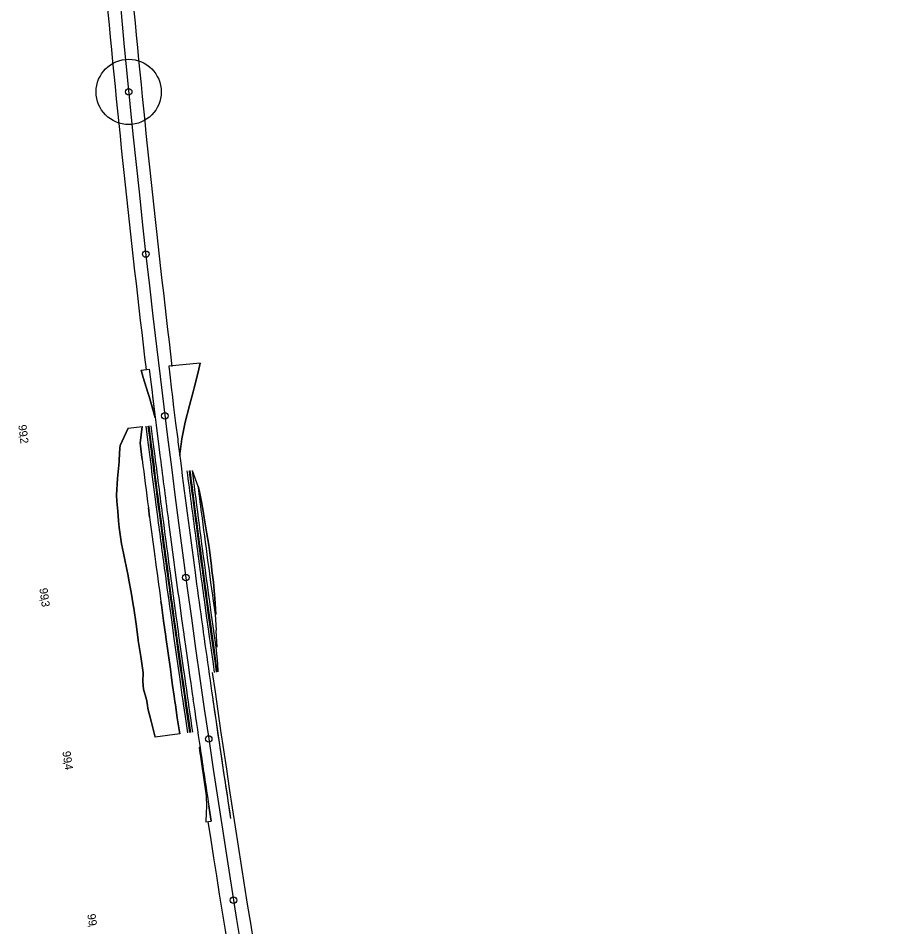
# Model space of a CAD drawing. Extents: x -678487 to -674601, y -1104811 to -1093295.
# Drawn here: x -677497 to -676952, y -1096306 to -1095749 of the extents above; entities that cross this region are included whole.
import ezdxf

# ---------------------------------------------------------------- set-up
doc = ezdxf.new("R2010")
doc.units = 0
for name, color, linetype in [('00_MiNGO', 7, 'Continuous'), ('SOxxxxxx_Osa_bod_P', 7, 'Continuous'), ('SOxxxxxx_Staničení_Popis', 7, 'Continuous'), ('SOxxxxxx_Staničení_Popis10', 7, 'Continuous'), ('SOxxxxxx_ŽSp_hrana', 7, 'Continuous'), ('SOxxxxxx_ŽSp_násyp_hrana', 7, 'Continuous'), ('SOxxxxxx_ŽSp_násyp_plocha', 7, 'Continuous'), ('SOxxxxxx_ŽSp_odvodnění', 7, 'Continuous'), ('SOxxxxxx_ŽSp_zářez_hrana', 7, 'Continuous'), ('SOxxxxxx_ŽSp_zářez_plocha', 7, 'Continuous')]:
    doc.layers.add(name, color=color, linetype=linetype)

msp = doc.modelspace()

# ---------------------------------------------------------------- linework, layer by layer
at = {"layer": '00_MiNGO'}
for radius, start, end in [(8494.25, 185.221143, 186.854762), (8510.25, 185.218154, 186.854762), (8494.25, 188.132648, 193.297784), (8510.25, 188.739149, 193.586695)]:
    msp.add_arc((-668968.6, -1094948.57), radius, start, end, dxfattribs=at)
at = {"layer": 'SOxxxxxx_Osa_bod_P'}
msp.add_arc((-668968.6, -1094948.57), 8502.25, 183.991255, 200.113006, dxfattribs=at)
at = {"layer": 'SOxxxxxx_Staničení_Popis'}
for p, q in [((-677428.71, -1095793.99), (-677428.71, -1095793.99)), ((-677418.18, -1095893.44), (-677418.18, -1095893.44)), ((-677406.48, -1095992.75), (-677406.48, -1095992.75)), ((-677393.62, -1096091.92), (-677393.62, -1096091.92)), ((-677379.59, -1096190.93), (-677379.59, -1096190.93)), ((-677364.39, -1096289.77), (-677364.39, -1096289.77))]:
    msp.add_line(p, q, dxfattribs=at)
for centre in [(-677428.71, -1095793.99), (-677418.18, -1095893.44), (-677406.48, -1095992.75), (-677393.62, -1096091.92), (-677379.59, -1096190.93), (-677364.39, -1096289.77)]:
    msp.add_circle(centre, 2, dxfattribs=at)
at = {"layer": 'SOxxxxxx_Staničení_Popis10'}
msp.add_line((-677428.71, -1095793.99), (-677428.71, -1095793.99), dxfattribs=at)
msp.add_circle((-677428.71, -1095793.99), 20, dxfattribs=at)
at = {"layer": 'SOxxxxxx_ŽSp_hrana'}
for p, q in [((-677416.04, -1095964.06), (-677415.47, -1095968.73)), ((-677415.47, -1095968.73), (-677414.33, -1095978.14)), ((-677414.33, -1095978.14), (-677414.04, -1095980.56)), ((-677414.04, -1095980.56), (-677413.06, -1095988.54)), ((-677413.06, -1095988.54), (-677411.83, -1095998.45)), ((-677411.83, -1095998.45), (-677410.59, -1096008.35)), ((-677410.59, -1096008.35), (-677410.4, -1096009.93)), ((-677410.4, -1096009.93), (-677409.49, -1096017.12)), ((-677409.49, -1096017.12), (-677409.35, -1096018.25)), ((-677387.98, -1096088.76), (-677387, -1096095.96)), ((-677397.59, -1096107.27), (-677396.22, -1096117.15)), ((-677396.22, -1096117.15), (-677394.9, -1096126.67)), ((-677394.9, -1096126.67), (-677394.85, -1096127.03)), ((-677394.85, -1096127.03), (-677393.46, -1096136.91)), ((-677382.97, -1096125.19), (-677382.92, -1096125.55)), ((-677393.46, -1096136.91), (-677392.06, -1096146.79)), ((-677392.06, -1096146.79), (-677391.32, -1096151.99)), ((-677391.32, -1096151.99), (-677390.65, -1096156.66)), ((-677390.65, -1096156.66), (-677389.72, -1096163.14)), ((-677389.72, -1096163.14), (-677389.23, -1096166.53)), ((-677379.51, -1096231.92), (-677378.88, -1096236.02)), ((-677378.88, -1096236.02), (-677378.07, -1096241.31))]:
    msp.add_line(p, q, dxfattribs=at)
for points in [[(-677404.15, -1095962.21), (-677403.51, -1095967.54), (-677402.37, -1095976.93), (-677402.08, -1095979.35), (-677401.1, -1095987.32), (-677399.88, -1095997.2), (-677398.64, -1096007.09), (-677398.44, -1096008.66), (-677397.54, -1096015.84)], [(-677378.73, -1096155.13), (-677377.8, -1096161.6), (-677377.31, -1096164.98)]]:
    msp.add_lwpolyline(points, dxfattribs=at)
for centre, radius, start, end in [((-668968.1, -1094948.47), 8496.75, 187.216621, 187.712543), ((-668969.09, -1094948.67), 8507.75, 187.222244, 187.491036), ((-668969.1, -1094948.67), 8507.75, 187.491036, 187.826977), ((-668968.09, -1094948.47), 8496.75, 187.761534, 187.960504), ((-668968.09, -1094948.47), 8496.75, 187.962972, 188.164393), ((-668969.1, -1094948.67), 8507.75, 188.230039, 188.431546), ((-668968.09, -1094948.47), 8496.75, 188.231529, 188.740385), ((-668969.1, -1094948.67), 8507.75, 188.431546, 188.675191)]:
    msp.add_arc(centre, radius, start, end, dxfattribs=at)
at = {"layer": 'SOxxxxxx_ŽSp_násyp_hrana'}
for p, q in [((-677384.85, -1095960.31), (-677386.16, -1095965.81)), ((-677421.13, -1095964.67), (-677419.76, -1095969.15)), ((-677386.16, -1095965.81), (-677388.5, -1095975.53)), ((-677419.76, -1095969.15), (-677416.94, -1095978.4)), ((-677388.5, -1095975.53), (-677389.16, -1095978.04)), ((-677416.94, -1095978.4), (-677416.23, -1095980.79)), ((-677416.23, -1095980.79), (-677413.93, -1095988.63)), ((-677389.16, -1095978.04), (-677391.32, -1095986.31)), ((-677391.32, -1095986.31), (-677393.99, -1095996.59)), ((-677393.99, -1095996.59), (-677396.09, -1096006.82)), ((-677396.33, -1096008.44), (-677397.23, -1096015.81)), ((-677396.09, -1096006.82), (-677396.33, -1096008.44)), ((-677397.23, -1096015.81), (-677397.36, -1096016.96)), ((-677378.73, -1096155.13), (-677377.8, -1096161.6)), ((-677377.8, -1096161.6), (-677377.31, -1096164.98)), ((-677377.31, -1096164.98), (-677377.01, -1096167.03)), ((-677377.01, -1096167.03), (-677375.88, -1096174.84)), ((-677375.88, -1096174.84), (-677374.43, -1096184.69)), ((-677374.43, -1096184.69), (-677372.98, -1096194.53)), ((-677372.98, -1096194.53), (-677372.37, -1096198.65)), ((-677385.53, -1096196.23), (-677385.04, -1096199.68)), ((-677385.04, -1096199.68), (-677384.93, -1096200.35)), ((-677384.93, -1096200.35), (-677384, -1096206.08)), ((-677372.37, -1096198.65), (-677371.51, -1096204.38)), ((-677384, -1096206.08), (-677382.66, -1096215.97)), ((-677371.51, -1096204.38), (-677370.04, -1096214.23)), ((-677382.66, -1096215.97), (-677381.15, -1096225.82)), ((-677370.04, -1096214.23), (-677368.55, -1096224.07)), ((-677381.15, -1096225.82), (-677380.9, -1096232.11)), ((-677368.55, -1096224.07), (-677367.61, -1096230.24)), ((-677380.9, -1096232.11), (-677381.07, -1096236.33)), ((-677367.61, -1096230.24), (-677366.98, -1096234.34)), ((-677366.98, -1096234.34), (-677366.17, -1096239.62)), ((-677381.07, -1096236.33), (-677381.29, -1096241.76))]:
    msp.add_line(p, q, dxfattribs=at)
at = {"layer": 'SOxxxxxx_ŽSp_násyp_plocha'}
for p, q in [((-677384.85, -1095960.31), (-677404.15, -1095962.21)), ((-677421.13, -1095964.67), (-677416.04, -1095964.06)), ((-677384.89, -1096196.14), (-677385.53, -1096196.23)), ((-677381.29, -1096241.76), (-677378.07, -1096241.31))]:
    msp.add_line(p, q, dxfattribs=at)
for points in [[(-677397.38, -1096017.05), (-677396.33, -1096008.44), (-677396.09, -1096006.82), (-677393.99, -1095996.59), (-677391.32, -1095986.31), (-677389.16, -1095978.04), (-677388.5, -1095975.53), (-677386.16, -1095965.81), (-677384.85, -1095960.31)], [(-677412.41, -1095993.85), (-677416.23, -1095980.79), (-677416.94, -1095978.4), (-677419.76, -1095969.15), (-677421.13, -1095964.67)], [(-677416.04, -1095964.06), (-677415.47, -1095968.73), (-677414.33, -1095978.14), (-677414.04, -1095980.56), (-677412.41, -1095993.85)], [(-677404.15, -1095962.21), (-677403.51, -1095967.54), (-677402.37, -1095976.93), (-677402.08, -1095979.35), (-677401.1, -1095987.32), (-677399.88, -1095997.2), (-677398.64, -1096007.09), (-677398.44, -1096008.66), (-677397.54, -1096015.84)], [(-677385.53, -1096196.23), (-677385.04, -1096199.68), (-677384.93, -1096200.35), (-677384, -1096206.08), (-677382.66, -1096215.97), (-677381.15, -1096225.82), (-677380.9, -1096232.11), (-677381.07, -1096236.33), (-677381.29, -1096241.76)], [(-677378.07, -1096241.31), (-677378.88, -1096236.02), (-677379.51, -1096231.92)]]:
    msp.add_lwpolyline(points, dxfattribs=at)
for centre, radius, start, end in [((-668968.1, -1094948.47), 8496.75, 187.216621, 187.224797), ((-668969.1, -1094948.67), 8507.75, 188.431546, 188.675191)]:
    msp.add_arc(centre, radius, start, end, dxfattribs=at)
at = {"layer": 'SOxxxxxx_ŽSp_odvodnění'}
for p, q in [((-677416.85, -1095998.97), (-677415.62, -1096008.88)), ((-677416.31, -1095998.91), (-677415.07, -1096008.82)), ((-677415.62, -1096008.88), (-677415.42, -1096010.46)), ((-677415.07, -1096008.82), (-677414.87, -1096010.4)), ((-677410.81, -1096042.19), (-677410, -1096048.44)), ((-677406.08, -1096078.13), (-677404.75, -1096088.03)), ((-677404.75, -1096088.03), (-677404.39, -1096090.7)), ((-677404.39, -1096090.7), (-677403.41, -1096097.92)), ((-677403.41, -1096097.92), (-677402.34, -1096105.72)), ((-677402.34, -1096105.72), (-677402.05, -1096107.81)), ((-677381.47, -1096103.2), (-677381.19, -1096105.29)), ((-677381.19, -1096105.29), (-677379.82, -1096115.14)), ((-677380.93, -1096103.14), (-677380.64, -1096105.22)), ((-677380.64, -1096105.22), (-677379.28, -1096115.08)), ((-677402.05, -1096107.81), (-677400.69, -1096117.7)), ((-677379.82, -1096115.14), (-677378.5, -1096124.64)), ((-677379.28, -1096115.08), (-677377.96, -1096124.57)), ((-677400.69, -1096117.7), (-677399.36, -1096127.22)), ((-677399.91, -1096127.29), (-677399.86, -1096127.65)), ((-677399.86, -1096127.65), (-677398.47, -1096137.54)), ((-677399.36, -1096127.22), (-677399.31, -1096127.59)), ((-677399.31, -1096127.59), (-677397.92, -1096137.47)), ((-677378.5, -1096124.64), (-677378.45, -1096125)), ((-677378.45, -1096125), (-677377.07, -1096134.85)), ((-677377.96, -1096124.57), (-677377.91, -1096124.93)), ((-677377.91, -1096124.93), (-677376.52, -1096134.78)), ((-677398.47, -1096137.54), (-677397.07, -1096147.42)), ((-677397.92, -1096137.47), (-677396.52, -1096147.35)), ((-677377.07, -1096134.85), (-677375.67, -1096144.7)), ((-677376.52, -1096134.78), (-677375.13, -1096144.64)), ((-677375.67, -1096144.7), (-677374.93, -1096149.89)), ((-677375.13, -1096144.64), (-677374.39, -1096149.82)), ((-677397.07, -1096147.42), (-677396.33, -1096152.63)), ((-677396.52, -1096147.35), (-677395.78, -1096152.56)), ((-677396.33, -1096152.63), (-677395.66, -1096157.31)), ((-677395.78, -1096152.56), (-677395.11, -1096157.24)), ((-677395.66, -1096157.31), (-677394.73, -1096163.79)), ((-677395.11, -1096157.24), (-677394.18, -1096163.72)), ((-677394.73, -1096163.79), (-677394.24, -1096167.19)), ((-677394.24, -1096167.19), (-677393.94, -1096169.24)), ((-677394.18, -1096163.72), (-677393.69, -1096167.11)), ((-677393.69, -1096167.11), (-677393.39, -1096169.17)), ((-677393.94, -1096169.24), (-677392.8, -1096177.06)), ((-677393.39, -1096169.17), (-677392.26, -1096176.99)), ((-677392.8, -1096177.06), (-677391.35, -1096186.94)), ((-677392.26, -1096176.99), (-677390.81, -1096186.87))]:
    msp.add_line(p, q, dxfattribs=at)
for centre, radius, start, end in [((-668969.51, -1094948.75), 8512.38, 187.164886, 187.380633), ((-668969.47, -1094948.74), 8511.87, 187.16498, 187.380722), ((-668967.72, -1094948.4), 8492.63, 187.292183, 187.56077), ((-668967.67, -1094948.39), 8492.13, 187.292275, 187.560855), ((-668969.51, -1094948.75), 8512.38, 187.380633, 187.557454), ((-668969.47, -1094948.74), 8511.87, 187.423125, 187.624742), ((-668967.72, -1094948.4), 8492.63, 187.56077, 187.81513), ((-668967.67, -1094948.39), 8492.13, 187.560855, 187.815209), ((-668969.51, -1094948.75), 8512.37, 187.557454, 187.759064), ((-668969.52, -1094948.75), 8512.37, 187.759064, 187.958184)]:
    msp.add_arc(centre, radius, start, end, dxfattribs=at)
at = {"layer": 'SOxxxxxx_ŽSp_zářez_hrana'}
for p, q in [((-677428.97, -1096000.23), (-677433.98, -1096010.82)), ((-677415.03, -1095998.78), (-677413.8, -1096008.69)), ((-677433.98, -1096010.82), (-677434.2, -1096012.44)), ((-677413.8, -1096008.69), (-677413.6, -1096010.26)), ((-677413.6, -1096010.26), (-677412.69, -1096017.46)), ((-677434.2, -1096012.44), (-677434.49, -1096019.79)), ((-677434.61, -1096020.95), (-677435.65, -1096031.14)), ((-677434.49, -1096019.79), (-677434.61, -1096020.95)), ((-677389.84, -1096026.17), (-677388.57, -1096036.03)), ((-677389.75, -1096026.15), (-677386.27, -1096035.78)), ((-677435.65, -1096031.14), (-677436.27, -1096041.29)), ((-677388.57, -1096036.03), (-677388.1, -1096039.68)), ((-677386.13, -1096035.77), (-677385.33, -1096039.37)), ((-677436.27, -1096041.29), (-677436.05, -1096044.99)), ((-677385.33, -1096039.37), (-677383.98, -1096045.53)), ((-677436.05, -1096044.99), (-677435.46, -1096051.28)), ((-677415.86, -1096054.91), (-677416.61, -1096049.18)), ((-677383.98, -1096045.53), (-677383, -1096051.21)), ((-677435.46, -1096051.28), (-677434.91, -1096057.05)), ((-677383, -1096051.21), (-677382.31, -1096055.35)), ((-677382.31, -1096055.35), (-677380.65, -1096065.17)), ((-677434.91, -1096057.05), (-677434.5, -1096061.26)), ((-677434.5, -1096061.26), (-677433.06, -1096071.18)), ((-677380.65, -1096065.17), (-677379.69, -1096070.85)), ((-677433.06, -1096071.18), (-677431.92, -1096076.89)), ((-677383.94, -1096071.34), (-677383.38, -1096075.49)), ((-677379.69, -1096070.85), (-677379.13, -1096075)), ((-677431.92, -1096076.89), (-677431.09, -1096081.04)), ((-677379.13, -1096075), (-677377.92, -1096084.87)), ((-677431.09, -1096081.04), (-677429.11, -1096090.9)), ((-677403.48, -1096087.88), (-677403.12, -1096090.55)), ((-677379.75, -1096085.08), (-677379.39, -1096087.75)), ((-677379.39, -1096087.75), (-677378.42, -1096094.94)), ((-677377.92, -1096084.87), (-677377.59, -1096087.53)), ((-677377.59, -1096087.53), (-677376.7, -1096094.73)), ((-677429.11, -1096090.9), (-677428.55, -1096093.56)), ((-677428.55, -1096093.56), (-677427.27, -1096100.77)), ((-677378.42, -1096094.94), (-677377.35, -1096102.71)), ((-677376.7, -1096094.73), (-677376.07, -1096102.55)), ((-677427.27, -1096100.77), (-677425.99, -1096108.57)), ((-677382.74, -1096103.36), (-677382.46, -1096105.44)), ((-677382.46, -1096105.44), (-677381.1, -1096115.3)), ((-677379.66, -1096102.98), (-677379.37, -1096105.07)), ((-677379.37, -1096105.07), (-677378.01, -1096114.92)), ((-677377.35, -1096102.71), (-677377.07, -1096104.79)), ((-677377.07, -1096104.79), (-677375.71, -1096114.64)), ((-677376.07, -1096102.55), (-677375.92, -1096104.65)), ((-677375.92, -1096104.65), (-677375.18, -1096114.58)), ((-677425.99, -1096108.57), (-677425.64, -1096110.66)), ((-677425.64, -1096110.66), (-677424.07, -1096120.56)), ((-677381.1, -1096115.3), (-677379.77, -1096124.8)), ((-677378.01, -1096114.92), (-677376.69, -1096124.41)), ((-677375.71, -1096114.64), (-677374.92, -1096124.19)), ((-677424.07, -1096120.56), (-677422.91, -1096130.14)), ((-677398.09, -1096127.07), (-677398.04, -1096127.43)), ((-677398.04, -1096127.43), (-677396.65, -1096137.31)), ((-677379.77, -1096124.8), (-677379.72, -1096125.16)), ((-677379.72, -1096125.16), (-677378.34, -1096135.01)), ((-677376.69, -1096124.41), (-677376.64, -1096124.77)), ((-677376.64, -1096124.77), (-677375.25, -1096134.63)), ((-677374.92, -1096124.19), (-677375.3, -1096124.61)), ((-677375.3, -1096124.61), (-677374.55, -1096134.52)), ((-677422.91, -1096130.14), (-677422.87, -1096130.51)), ((-677422.87, -1096130.51), (-677421.33, -1096140.39)), ((-677396.65, -1096137.31), (-677395.25, -1096147.19)), ((-677378.34, -1096135.01), (-677376.94, -1096144.87)), ((-677375.25, -1096134.63), (-677374.27, -1096144.53)), ((-677374.55, -1096134.52), (-677374.55, -1096134.54)), ((-677421.33, -1096140.39), (-677421.33, -1096140.41)), ((-677421.33, -1096140.41), (-677419.79, -1096150.31)), ((-677376.94, -1096144.87), (-677376.2, -1096150.06)), ((-677374.27, -1096144.53), (-677373.98, -1096149.77)), ((-677419.79, -1096150.31), (-677420.12, -1096155.67)), ((-677395.25, -1096147.19), (-677394.51, -1096152.4)), ((-677420.12, -1096155.67), (-677419.52, -1096160.37)), ((-677394.51, -1096152.4), (-677393.84, -1096157.07)), ((-677419.52, -1096160.37), (-677417.76, -1096166.78)), ((-677417.76, -1096166.78), (-677417.1, -1096170.16)), ((-677417.1, -1096170.16), (-677416.87, -1096172.23)), ((-677416.87, -1096172.23), (-677414.97, -1096179.98)), ((-677414.97, -1096179.98), (-677412.4, -1096189.74))]:
    msp.add_line(p, q, dxfattribs=at)
for points in [[(-677420.43, -1096019.44), (-677420.57, -1096018.31), (-677421.48, -1096011.1), (-677421.68, -1096009.52), (-677420.43, -1095999.34)], [(-677418.13, -1095999.1), (-677416.89, -1096009.01), (-677416.69, -1096010.59), (-677415.78, -1096017.79)], [(-677412.63, -1096042.39), (-677411.82, -1096048.64), (-677411.07, -1096054.37)], [(-677406.57, -1096088.24), (-677406.21, -1096090.92), (-677405.22, -1096098.14), (-677404.16, -1096105.94), (-677403.87, -1096108.03), (-677402.51, -1096117.92), (-677401.18, -1096127.45), (-677401.13, -1096127.81), (-677399.74, -1096137.7), (-677398.34, -1096147.59), (-677397.6, -1096152.79), (-677396.93, -1096157.47), (-677395.99, -1096163.96), (-677395.5, -1096167.35), (-677395.21, -1096169.41), (-677394.07, -1096177.23), (-677392.62, -1096187.11)], [(-677397.4, -1096187.75), (-677398.85, -1096177.86), (-677399.99, -1096170.03), (-677400.28, -1096167.97), (-677400.77, -1096164.58), (-677401.71, -1096158.08), (-677402.38, -1096153.4), (-677403.12, -1096148.19), (-677404.52, -1096138.3), (-677405.91, -1096128.4), (-677405.96, -1096128.04), (-677407.29, -1096118.51), (-677408.66, -1096108.61), (-677408.94, -1096106.52)]]:
    msp.add_lwpolyline(points, dxfattribs=at)
for centre, radius, start, end in [((-668970.02, -1094948.85), 8517.96, 187.220371, 187.422067), ((-668969.62, -1094948.77), 8513.55, 187.213524, 187.380427), ((-668969.36, -1094948.72), 8510.7, 187.214048, 187.490533), ((-668967.83, -1094948.42), 8493.8, 187.291971, 187.560573), ((-668967.37, -1094948.33), 8488.83, 187.360011, 187.49428), ((-668967.57, -1094948.37), 8490.96, 187.384414, 187.599914), ((-668970.02, -1094948.85), 8517.96, 187.460929, 187.623744), ((-668969.62, -1094948.77), 8513.55, 187.461686, 187.691674), ((-668967.37, -1094948.33), 8488.84, 187.49428, 187.695666), ((-668969.36, -1094948.72), 8510.7, 187.490533, 187.692132), ((-668967.83, -1094948.42), 8493.8, 187.560573, 187.814947), ((-668967.57, -1094948.37), 8490.96, 187.628188, 187.815392), ((-668970.02, -1094948.85), 8517.96, 187.623744, 187.811192), ((-668969.36, -1094948.72), 8510.7, 187.710304, 187.958433), ((-668969.37, -1094948.72), 8510.7, 188.162459, 188.364)]:
    msp.add_arc(centre, radius, start, end, dxfattribs=at)
at = {"layer": 'SOxxxxxx_ŽSp_zářez_plocha'}
for p, q in [((-677428.97, -1096000.23), (-677420.43, -1095999.34)), ((-677386.13, -1096035.77), (-677386.27, -1096035.78)), ((-677416.61, -1096049.18), (-677415.86, -1096054.91)), ((-677375.71, -1096114.64), (-677375.18, -1096114.58)), ((-677397.4, -1096187.75), (-677412.4, -1096189.74))]:
    msp.add_line(p, q, dxfattribs=at)
for points in [[(-677412.4, -1096189.74), (-677414.97, -1096179.98), (-677416.87, -1096172.23), (-677417.1, -1096170.16), (-677417.76, -1096166.78), (-677419.52, -1096160.37), (-677420.12, -1096155.67), (-677419.79, -1096150.31), (-677421.33, -1096140.41), (-677421.33, -1096140.39), (-677422.87, -1096130.51), (-677422.91, -1096130.14), (-677424.07, -1096120.56), (-677425.64, -1096110.66), (-677425.99, -1096108.57), (-677427.27, -1096100.77), (-677428.55, -1096093.56), (-677429.11, -1096090.9), (-677431.09, -1096081.04), (-677431.92, -1096076.89), (-677433.06, -1096071.18), (-677434.5, -1096061.26), (-677434.91, -1096057.05), (-677435.46, -1096051.28), (-677436.05, -1096044.99), (-677436.27, -1096041.29), (-677435.65, -1096031.14), (-677434.61, -1096020.95), (-677434.49, -1096019.79), (-677434.2, -1096012.44), (-677433.98, -1096010.82), (-677428.97, -1096000.23)], [(-677420.43, -1095999.34), (-677421.68, -1096009.52), (-677421.48, -1096011.1), (-677420.57, -1096018.31), (-677420.43, -1096019.44)], [(-677375.18, -1096114.58), (-677375.92, -1096104.65), (-677376.07, -1096102.55), (-677376.7, -1096094.73), (-677377.59, -1096087.53), (-677377.92, -1096084.87), (-677379.13, -1096075), (-677379.69, -1096070.85), (-677380.65, -1096065.17), (-677382.31, -1096055.35), (-677383, -1096051.21), (-677383.98, -1096045.53), (-677385.33, -1096039.37), (-677386.13, -1096035.77)], [(-677379.75, -1096085.08), (-677379.39, -1096087.75), (-677378.42, -1096094.94), (-677377.35, -1096102.71), (-677377.07, -1096104.79), (-677375.71, -1096114.64)], [(-677408.94, -1096106.52), (-677408.66, -1096108.61), (-677407.29, -1096118.51), (-677405.96, -1096128.04), (-677405.91, -1096128.4), (-677404.52, -1096138.3), (-677403.12, -1096148.19), (-677402.38, -1096153.4), (-677401.71, -1096158.08), (-677400.77, -1096164.58), (-677400.28, -1096167.97), (-677399.99, -1096170.03), (-677398.85, -1096177.86), (-677397.4, -1096187.75)]]:
    msp.add_lwpolyline(points, dxfattribs=at)
for centre, radius, start, end in [((-668970.02, -1094948.85), 8517.96, 187.220371, 187.422067), ((-668967.37, -1094948.33), 8488.83, 187.360011, 187.49428), ((-668970.02, -1094948.85), 8517.96, 187.460929, 187.623744), ((-668967.37, -1094948.33), 8488.84, 187.49428, 187.695666), ((-668970.02, -1094948.85), 8517.96, 187.623744, 187.811192)]:
    msp.add_arc(centre, radius, start, end, dxfattribs=at)

# ---------------------------------------------------------------- texts
at = {"layer": 'SOxxxxxx_Staničení_Popis'}
for s, rotation, p in [('99', 277.0544, (-677496.47, -1095998.42)), (',', 277.0544, (-677495.69, -1096004.74)), ('2', 277.0544, (-677495.49, -1096006.33)), ('99', 277.7283, (-677483.53, -1096098.63)), (',', 277.7283, (-677482.68, -1096104.94)), ('3', 277.7283, (-677482.46, -1096106.52)), ('99', 278.4022, (-677469.42, -1096198.7)), (',', 278.4022, (-677468.49, -1096205.01)), ('4', 278.4022, (-677468.25, -1096206.58)), ('99', 279.0761, (-677454.13, -1096298.58)), (',', 279.0761, (-677453.12, -1096304.87))]:
    msp.add_text(s, height=5, rotation=rotation, dxfattribs=at).set_placement(p)

doc.saveas('drawing.dxf')
